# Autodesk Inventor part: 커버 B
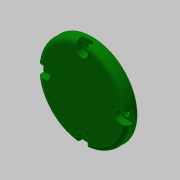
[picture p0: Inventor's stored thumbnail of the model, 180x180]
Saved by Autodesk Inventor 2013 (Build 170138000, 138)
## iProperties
Created: 2019-05
Part Number: 커버 B
Material: 알루미늄 6061
Document SubType Name: Modeling
Designer: mduedu
Density: 2.71 g/cm^3
Mass: 59.5305 g
Surface Area: 80.458 cm^2
Volume: 21.967 cm^3
Author: mduedu
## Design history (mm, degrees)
sketch "스케치1"
  geometry: C1 r 31 at (0, 0); 1 further point
  constraints: 1 centre point, 1 coincident
  dimensions: "d0" = 62 diameter of C1
extrude "돌출1" new body sketch "스케치1" distance "d1" = 7; taper "d2" = 0 deg
sketch "스케치3"
  geometry: C1 r 20 at (0, 0); 1 further point
  constraints: 1 centre point, 1 coincident
  dimensions: "d7" = 40 diameter of C1
extrude "돌출3" join sketch "스케치3" distance "d8" = 4; taper "d9" = 0 deg
sketch "스케치4"
  geometry: C1 r 17 at (0, 0); 1 further point
  constraints: 1 centre point, 1 coincident
  dimensions: "d10" = 34 diameter of C1
extrude "돌출4" cut sketch "스케치4" distance "d11" = 3; taper "d12" = 0 deg
fillet "모깎기3" dims "d20" = 3
fillet "모깎기4" dims "d21" = 3
chamfer "모따기1" distance "d22" = 1; stored, may be unused: second distance "d23" = 2, angle "d24" = 45 deg
sketch "스케치7" dims "d25" = 52
  geometry: L1 (-4, 26)-(-4, 30.741); L2 (4, 26)-(4, 30.741); A1 r 4 centre (0, 26) between (-4, 26) and (4, 26); A2 r 31 centre (0, 0) between (4, 30.741) and (-4, 30.741); 3 further points
  constraints: 4 end point, 4 point on circle, 2 centre point, 2 coincident, 2 tangent, 2 vertical alignment, 1 parallel, 1 vertical, 4 other
  dimensions: "d26" = 8 distance between parallel lines of L2 L1
extrude "돌출7" cut sketch "스케치7" distance "d27" = 4.4; taper "d28" = 0 deg
sketch "스케치8" dims "d36" = 52
  geometry: 6 further points
  constraints: 2 vertical alignment, 1 coincident, 7 other
  dimensions: "d39" = 360 deg dimension on point (0, 0) point (0, 26) (derived)
sketch "스케치9"
  geometry: 4 further points
  constraints: 4 other
hole "구멍1" sketch "스케치9" at (0, 52), (-26, 26), (26, 26), (0, 0) diameter "d41" = 4.5; stored, may be unused: countersink angle "d45" = 90 deg, drill point angle "d47" = 0 deg; dims "d42" = 6, "d43" = 4, "d44" = 2, "d46" = 8
node "솔리드1"
pattern_circular "원형 패턴1" dims angle "d30" = 360 deg
